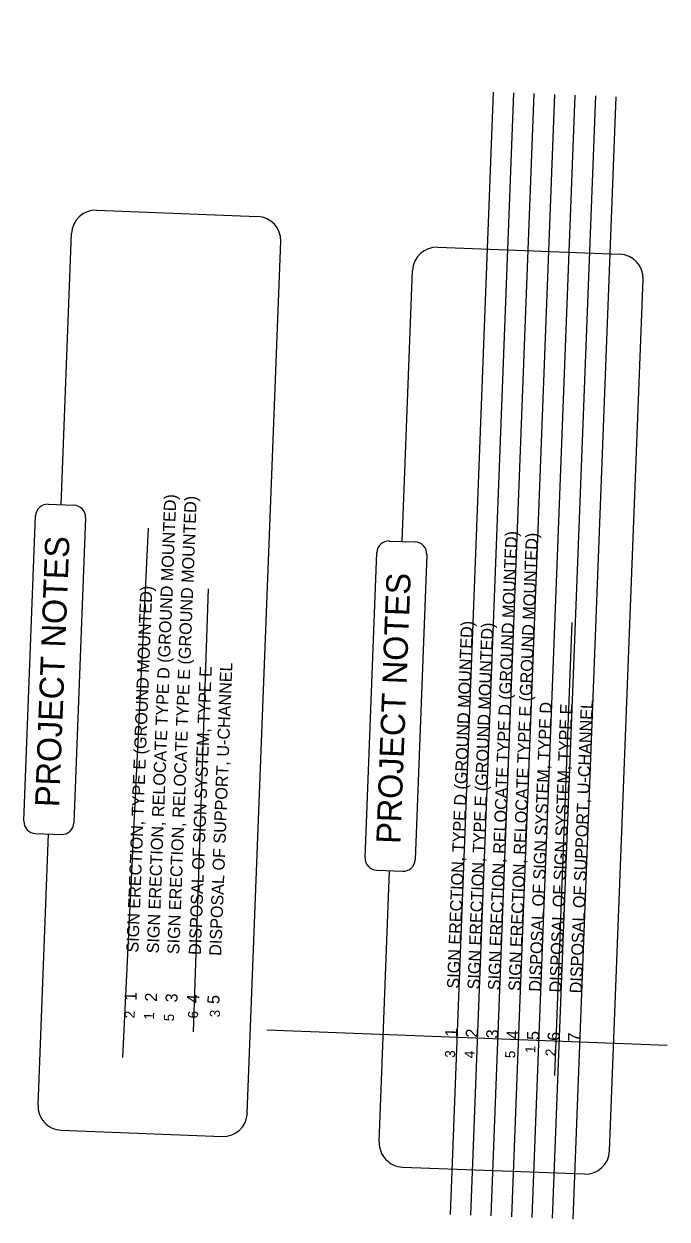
# Model space of a CAD drawing. Extents: x 2096670 to 2098561, y 684033 to 689893.
# Drawn here: x 2096670 to 2097309, y 684033 to 685221 of the extents above; entities that cross this region are included whole.
import ezdxf

# ---------------------------------------------------------------- set-up
doc = ezdxf.new("R2010")
doc.units = 0
for name, color, linetype in [('Default', 7, 'Continuous'), ('Exist Sign E Speed Limit XX CELL', 7, 'Continuous'), ('Scratch_Level_2', 7, 'Continuous'), ('Scratch_Level_3', 7, 'Continuous'), ('Scratch_Level_5', 7, 'Continuous'), ('Sheet Title CELL', 7, 'Continuous')]:
    doc.layers.add(name, color=color, linetype=linetype)

msp = doc.modelspace()

# ---------------------------------------------------------------- linework, layer by layer
at = {"layer": 'Scratch_Level_2'}
for p, q in [((2097094.1, 684038), (2097136.9, 685153)), ((2097114.4, 684037.2), (2097157.2, 685152.2)), ((2097134.7, 684036.4), (2097177.5, 685151.4)), ((2097155.1, 684035.6), (2097197.8, 685150.6)), ((2097175.4, 684034.9), (2097218.1, 685149.9)), ((2097195.7, 684034.1), (2097238.5, 685149.1)), ((2097216, 684033.3), (2097258.8, 685148.3)), ((2096911.7, 684221.4), (2097309.4, 684206.1))]:
    msp.add_line(p, q, dxfattribs=at)
at = {"layer": 'Scratch_Level_3'}
for p, q in [((2096768.8, 684194), (2096794.1, 684719.8)), ((2096838.9, 684219.2), (2096853.9, 684659.4)), ((2097197.9, 684176.1), (2097215.1, 684625.9))]:
    msp.add_line(p, q, dxfattribs=at)
at = {"layer": 'Sheet Title CELL'}
for p, q in [((2096742.6, 685035.5), (2096902.5, 685029.3)), ((2096707.3, 684743), (2096717.7, 685012.4)), ((2096892.3, 684138.5), (2096925.5, 685004.4)), ((2097081.5, 684998.9), (2097262.4, 684992)), ((2097046.3, 684706.5), (2097056.6, 684975.8)), ((2097252.3, 684101.1), (2097285.5, 684967.1)), ((2096694.5, 684743.5), (2096720.2, 684742.5)), ((2096670.4, 684428.8), (2096682, 684732)), ((2096731.7, 684730.1), (2096720.1, 684426.9)), ((2097033.4, 684706.9), (2097059.1, 684706)), ((2097009.4, 684392.2), (2097021, 684695.4)), ((2097070.7, 684693.5), (2097059, 684390.3)), ((2096681.9, 684416.3), (2096707.6, 684415.4)), ((2096684.5, 684146.5), (2096694.8, 684415.9)), ((2097020.9, 684379.8), (2097046.6, 684378.8)), ((2097023.4, 684109.9), (2097033.7, 684379.3)), ((2096707.5, 684121.6), (2096867.4, 684115.4)), ((2097046.5, 684085), (2097227.4, 684078.1))]:
    msp.add_line(p, q, dxfattribs=at)
for centre, radius, start, end in [((2096741.6, 685011.5), 24, 87.8037, 177.8037), ((2096901.6, 685005.4), 24, 357.8037, 87.8037), ((2097080.6, 684974.9), 24, 87.8037, 177.8037), ((2097261.5, 684968), 24, 357.8037, 87.8037), ((2096694, 684731.5), 12, 87.8037, 177.8037), ((2096719.7, 684730.5), 12, 357.8037, 87.8037), ((2097033, 684695), 12, 87.8037, 177.8037), ((2097058.7, 684694), 12, 357.8037, 87.8037), ((2096682.4, 684428.3), 12, 177.8037, 267.8037), ((2096708.1, 684427.4), 12, 267.8037, 357.8037), ((2097021.4, 684391.8), 12, 177.8037, 267.8037), ((2097047, 684390.8), 12, 267.8037, 357.8037), ((2096708.4, 684145.6), 24, 177.8037, 267.8037), ((2096868.4, 684139.4), 24, 267.8037, 357.8037), ((2097047.4, 684109), 24, 177.8037, 267.8037), ((2097228.3, 684102), 24, 267.8037, 357.8037)]:
    msp.add_arc(centre, radius, start, end, dxfattribs=at)

# ---------------------------------------------------------------- texts
at = {"layer": 'Default'}
for s, height, p in [('SIGN ERECTION, RELOCATE TYPE D (GROUND MOUNTED)', 12, (2096804.4, 684297.1)), ('SIGN ERECTION, RELOCATE TYPE E (GROUND MOUNTED)', 12, (2096824.7, 684296.3)), ('PROJECT NOTES', 24, (2096705.4, 684442.3)), ('SIGN ERECTION, RELOCATE TYPE D (GROUND MOUNTED)', 12, (2097143.3, 684260.5)), ('SIGN ERECTION, RELOCATE TYPE E (GROUND MOUNTED)', 12, (2097163.7, 684259.7)), ('PROJECT NOTES', 24, (2097044.4, 684405.8)), ('SIGN ERECTION, TYPE E (GROUND MOUNTED)', 12, (2096784.1, 684297.9)), ('SIGN ERECTION, TYPE D (GROUND MOUNTED)', 12, (2097102.7, 684262.1)), ('SIGN ERECTION, TYPE E (GROUND MOUNTED)', 12, (2097123, 684261.3)), ('DISPOSAL OF SIGN SYSTEM, TYPE E', 12, (2096846.1, 684295.5)), ('DISPOSAL OF SUPPORT, U-CHANNEL', 12, (2096866.4, 684294.7)), ('DISPOSAL OF SIGN SYSTEM, TYPE D', 12, (2097184, 684259)), ('DISPOSAL OF SIGN SYSTEM, TYPE E', 12, (2097204.3, 684258.2)), ('DISPOSAL OF SUPPORT, U-CHANNEL', 12, (2097224.6, 684257.4)), ('1', 12, (2096782.2, 684249.9)), ('2', 12, (2096802.5, 684249.1)), ('3', 12, (2096822.9, 684248.4)), ('4', 12, (2096844.3, 684247.5)), ('5', 12, (2096864.6, 684246.8)), ('1', 12, (2097100.8, 684214.1)), ('2', 12, (2097121.2, 684213.3)), ('3', 12, (2097141.5, 684212.6)), ('4', 12, (2097161.8, 684211.8)), ('5', 12, (2097182.1, 684211)), ('6', 12, (2097202.5, 684210.2)), ('7', 12, (2097222.8, 684209.4))]:
    msp.add_text(s, height=height, rotation=87.8037, dxfattribs=at).set_placement(p)
at = {"layer": 'Exist Sign E Speed Limit XX CELL'}
for s in ['panelStyle:regulatory.ssi', 'panelName:R2-1', 'panelQuantity:1', 'panelStation:none', 'panelMaterial:0', 'legendMaterial:0', 'panelMounting:0', 'panelWidthLock:1', 'panelHeightLock:1', 'panelRoundCorners:0', 'panelSizes:MIN.:18x24,STD.:24x30,EXP:36x48,FWY.:48x60', 'constructPanelMode:0', 'constructPanels:36|24|18', 'marginAlign:9']:
    msp.add_text(s, height=0.000979, rotation=88.3526, dxfattribs=at).set_placement((2097097.2, 685220.6))
at = {"layer": 'Scratch_Level_5'}
for s, p in [('2', (2096780.4, 684232.6)), ('1', (2096799.6, 684231.2)), ('5', (2096819.4, 684229.6)), ('6', (2096843.3, 684232.5)), ('3', (2096865, 684233.6)), ('3', (2097098.7, 684193.4)), ('4', (2097118, 684193)), ('5', (2097158.4, 684193)), ('1', (2097178.3, 684198.1)), ('2', (2097198.5, 684194.9))]:
    msp.add_text(s, height=10, rotation=87.8037, dxfattribs=at).set_placement(p)

doc.saveas('drawing.dxf')
